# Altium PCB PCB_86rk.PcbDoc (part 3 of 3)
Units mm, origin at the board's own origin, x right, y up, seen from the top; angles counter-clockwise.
Board outline 185 x 150 mm, 2 copper layers (Top Layer, Bottom Layer); 95 components, 233 nets, 810 pads, 336 vias.
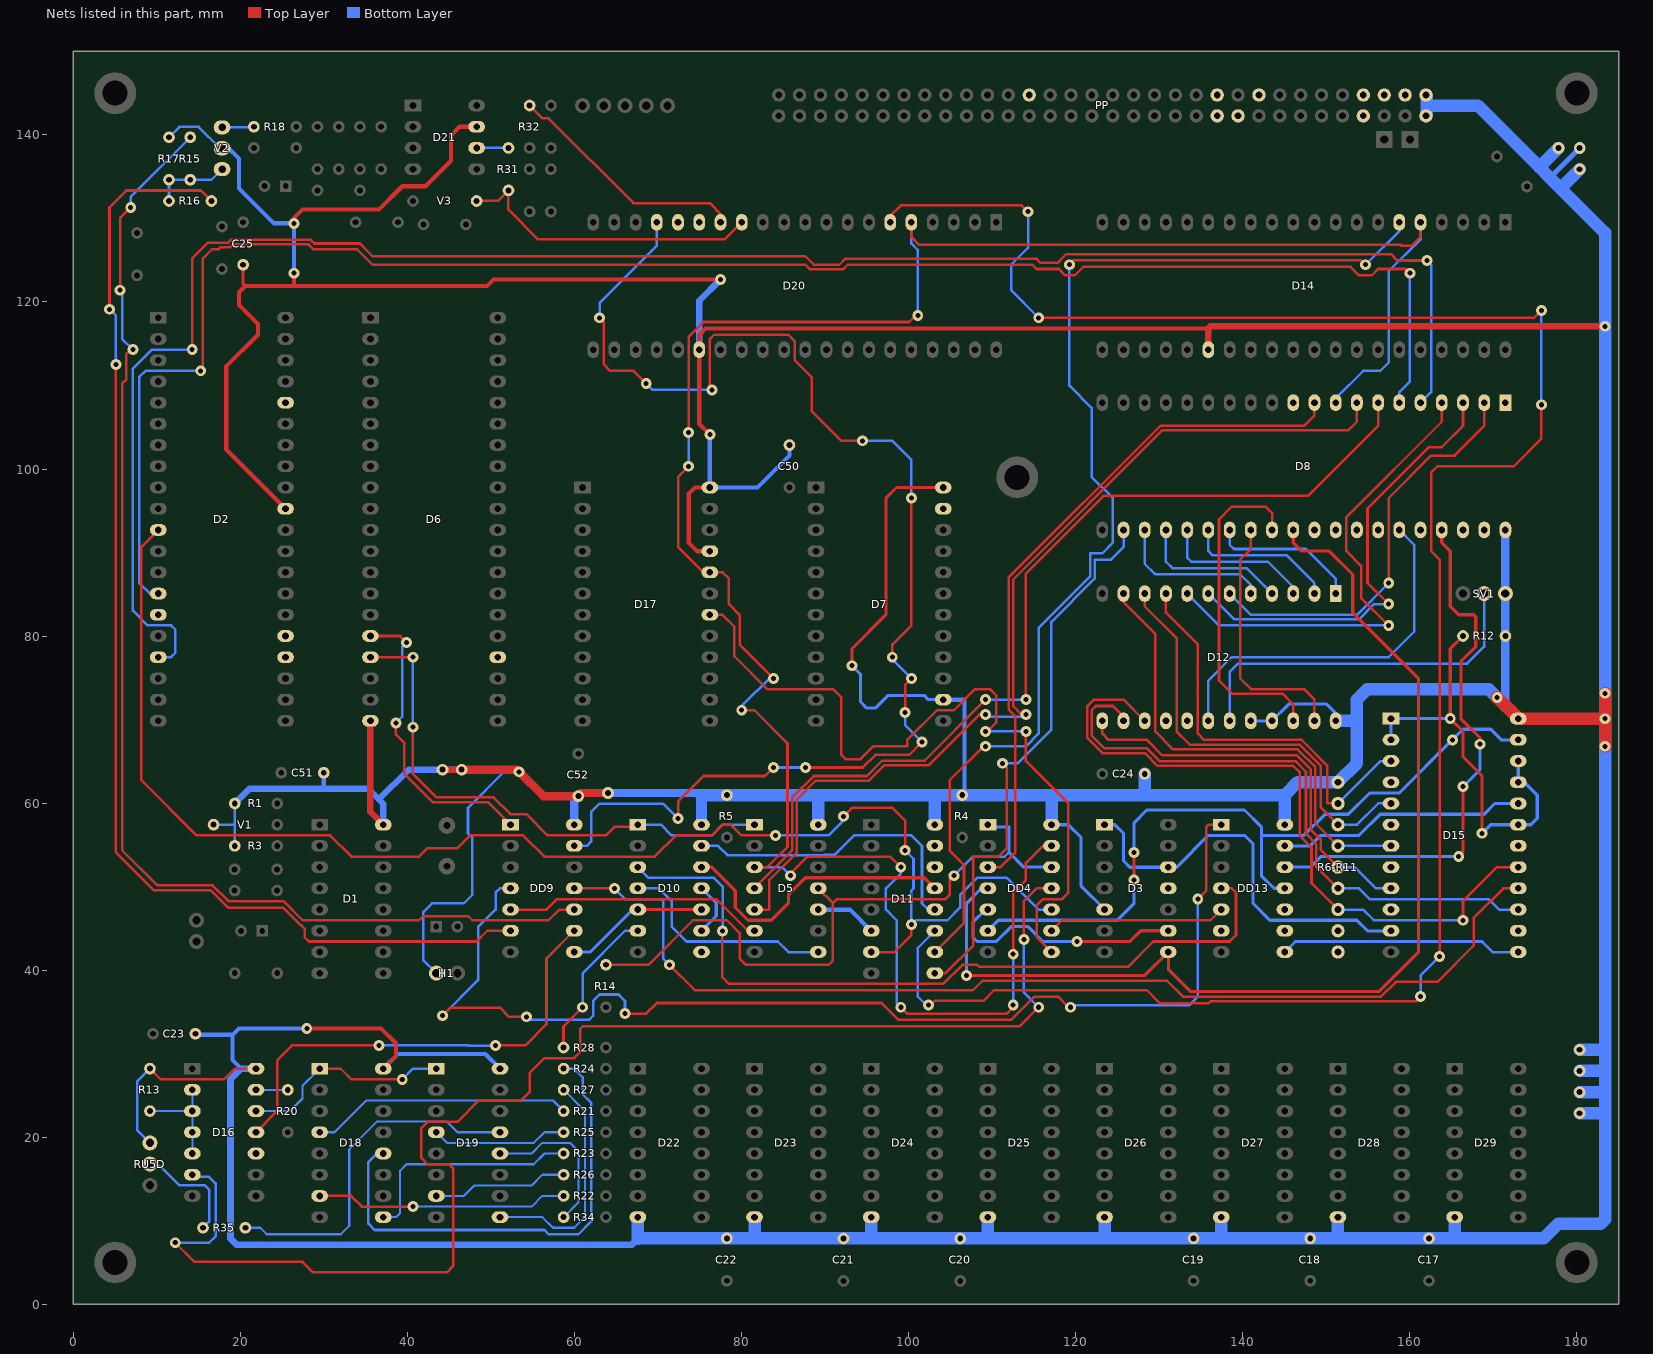
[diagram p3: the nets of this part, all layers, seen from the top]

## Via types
v1: diameter 1.3, hole 0.6, Top Layer to Bottom Layer, tented both sides, 301 vias
v2: diameter 1.4, hole 0.7, Top Layer to Bottom Layer, 27 vias
v3: diameter 1.4, hole 0.7, Top Layer to Bottom Layer, tented both sides, 4 vias
v4: diameter 3.2, hole 2.6, Top Layer to Bottom Layer, 2 vias
v5: diameter 1.6, hole 0.8, Top Layer to Bottom Layer, 1 vias
v6: diameter 1.6, hole 0.8, Top Layer to Bottom Layer, tented both sides, 1 vias

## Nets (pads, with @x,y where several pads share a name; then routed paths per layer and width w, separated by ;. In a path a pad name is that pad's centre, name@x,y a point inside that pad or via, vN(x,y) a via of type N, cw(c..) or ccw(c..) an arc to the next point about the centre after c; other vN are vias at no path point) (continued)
NetD2_11: D2.11 D11.7 DD4.10 | length 174
  Top Layer w0.305: D2.11@10.16,92.71 8.128,90.678 8.128,62.738 14.732,56.134 30.734,56.134 33.274,53.594 41.402,53.594 42.418,54.61 45.974,54.61 47.498,56.134 53.848,56.134 56.388,53.594 69.596,53.594 72.136,56.134 76.454,56.134 77.724,57.404 78.74,57.404 80.01,56.134 v1(84.074,56.134) ; v1(92.202,58.42) 93.218,59.436 98.044,59.436 99.568,57.912 v1(99.568,54.356) ; D11.7@95.52,42.18 95.536,42.164 98.298,42.164 100.33,44.196 v1(100.33,45.466)
  Bottom Layer w0.305: v1(84.074,56.134) 90.424,56.134 92.202,57.912 v1(92.202,58.42) ; v1(99.568,54.356) 100.584,53.34 100.584,49.784 100.33,49.53 v1(100.33,45.466) 100.838,45.974 104.648,45.974 106.172,47.498 106.172,49.022 108.204,51.054 111.76,51.054 115.554,47.26 DD4.10@117.11,47.26
NetD2_14: D2.14 D8.6 | length 213.3
  Top Layer w0.305: v1(15.24,111.76) 15.494,112.014 15.494,125.222 16.561,126.289 17.345,126.289 17.599,126.543 18.736,126.543 19.079,126.886 28.165,126.886 28.762,126.289 33.985,126.289 35.814,124.46 87.63,124.46 88.189,123.901 92.151,123.901 92.71,124.46 114.808,124.46 115.316,123.952 117.983,123.952 118.745,123.19 119.888,123.19 120.904,124.206 152.908,124.206 153.924,123.19 155.448,123.19 156.21,123.952 159.512,123.952 v1(160.02,123.444)
  Bottom Layer w0.305: D2.14@10.16,85.09 9.144,85.09 7.874,86.36 7.874,110.998 8.636,111.76 v1(15.24,111.76) ; D8.6@158.75,107.95 158.75,109.22 160.02,110.49 v1(160.02,123.444)
NetD2_15: D2.15
NetD2_17: D2.17 D8.5 | length 228
  Top Layer w0.305: v1(14.224,114.3) 14.224,125.222 16.104,127.102 18.505,127.102 18.848,127.444 28.396,127.444 28.841,127 34.29,127 35.814,125.476 87.63,125.476 88.646,124.46 91.694,124.46 92.405,125.171 115.316,125.171 115.814,124.674 117.816,124.674 118.872,125.73 157.734,125.73 158.496,124.968 v1(162.052,124.968)
  Bottom Layer w0.305: D2.17@10.16,77.47 11.684,77.47 12.192,77.978 12.192,80.772 11.684,81.28 8.89,81.28 7.112,83.058 7.112,112.014 9.398,114.3 v1(14.224,114.3) ; D8.5@161.29,107.95 162.56,109.22 162.56,124.46 v1(162.052,124.968)
NetD2_24: D2.24
NetD2_25: D2.25
NetD2_36: D2.36
NetD3_1: D3.1 D3.12 D15.11 | length 48.8
  Bottom Layer w0.381: D3.1@123.46,57.42 124.698,57.42 125.73,56.388 125.73,53.086 126.492,52.324 131.064,52.324 D3.12@131.08,52.34 132.096,52.34 135.89,56.134 140.208,56.134 141.224,55.118 141.224,48.006 143.256,45.974 153.67,45.974 154.94,44.704 157.734,44.704 D15.11@157.75,44.72
NetD3_8: D3.8 D8.30 DD4.4 | length 131
  Top Layer w0.381: v1(106.934,39.37) 128.27,39.37 D3.8@131.08,42.18 131.096,42.164 131.096,40.1 133.769,37.427 156.299,37.427 161.036,42.164 161.036,74.93 153.162,82.804 153.162,87.376 150.368,90.17 147.066,90.17 146.05,91.186 D8.30@146.05,92.71
  Bottom Layer w0.381: v1(106.934,39.37) 106.934,48.006 108.728,49.8 DD4.4@109.49,49.8
NetD3_9: D3.9 DD4.5 | length 29.8
  Top Layer w0.381: v1(120.142,43.434) 126.492,43.434 127.778,44.72 D3.9@131.08,44.72
  Bottom Layer w0.381: DD4.5@109.49,47.26 109.236,47.26 107.696,45.72 107.696,43.942 108.204,43.434 110.49,43.434 112.268,45.212 114.3,45.212 116.078,43.434 v1(120.142,43.434)
NetD3_11: D3.11
NetD5_1: D5.1 D6.17 D10.1 | length 64.6
  Top Layer w0.305: D6.17@35.56,77.47 v1(40.64,77.47) ; v1(40.64,69.088) 40.64,63.508 43.467,60.681 50.317,60.681 52.324,58.674 54.229,58.674 56.769,56.134 63.754,56.134 64.77,57.15 67.31,57.15 D10.1@67.58,57.42
  Bottom Layer w0.305: v1(40.64,69.088) v1(40.64,77.47) ; D10.1@67.58,57.42 70.342,57.42 71.628,56.134 76.454,56.134 77.74,57.42 D5.1@81.55,57.42
NetD5_3: D5.3 D8.9 D14.5 D17.20 D20.5 DD4.13 | length 284.2
  Top Layer w0.305: v1(73.66,100.33) 72.39,99.06 72.39,90.678 75.438,87.63 D17.20@76.2,87.63 77.724,87.63 78.486,86.868 78.486,83.82 79.756,82.55 79.756,78.994 v1(83.82,74.93) ; v1(73.66,104.394) 73.66,115.824 75.438,117.602 100.076,117.602 v1@101.092,118.618 ; v1(80.01,71.12) 81.534,71.12 85.496,67.158 85.496,54.762 83.074,52.34 D5.3@81.55,52.34 ; v1(85.852,51.308) 85.852,51.562 87.884,53.594 97.79,53.594 v1(99.06,52.324) ; v1(99.06,35.56) 99.862,34.758 111.72,34.758 v1@112.522,35.56 ; D20.5@100.33,129.54 100.33,127.762 101.244,126.848 158.902,126.848 159.004,126.746 160.274,126.746 161.29,127.762 D14.5@161.29,129.54 ; v1@113.03,41.91 112.522,42.418 112.522,49.276 114.046,50.8 114.046,52.832 116.094,54.88 DD4.13@117.11,54.88
  Bottom Layer w0.305: v1(73.66,100.33) v1(73.66,104.394) ; v1(80.01,71.12) 80.01,71.628 83.566,75.184 v1(83.82,74.93) ; D5.3@81.55,52.34 84.82,52.34 v1(85.852,51.308) ; v1(99.06,35.56) 98.552,36.068 98.552,45.974 97.282,47.244 97.282,49.784 99.06,51.562 v1(99.06,52.324) ; D20.5@100.33,129.54 100.33,127 101.092,126.238 v1(101.092,118.364) ; v1@112.522,35.56 v1(112.522,35.814) v1(112.522,41.91) ; D8.9@151.13,107.95 151.13,108.458 154.432,111.76 156.464,111.76 157.48,112.776 157.48,123.698 161.29,127.508 D14.5@161.29,129.54
NetD5_4: D5.4 D8.7 | length 112.9
  Top Layer w0.305: D5.4@81.55,49.8 81.55,49.828 86.055,54.333 86.055,60.655 88.646,63.246 94.996,63.246 96.825,65.075 101.905,65.075 v1(109.22,72.39) ; v1(114.046,72.39) 114.046,87.489 123.331,96.774 147.828,96.774 156.21,105.156 D8.7@156.21,107.95
  Bottom Layer w0.305: v1(109.22,72.39) v1(114.046,72.39)
NetD5_5: D5.5 D8.8 | length 116.3
  Top Layer w0.305: D5.5@81.55,47.26 83.328,47.26 83.312,47.276 83.312,50.8 86.614,54.102 86.614,60.424 88.877,62.687 95.227,62.687 97.056,64.516 102.362,64.516 108.458,70.612 v1(109.22,70.612) ; v1(114.046,70.612) 113.538,70.612 112.522,71.628 112.522,86.755 130.415,104.648 152.654,104.648 153.67,105.664 D8.8@153.67,107.95
  Bottom Layer w0.305: v1@109.22,70.358 v1@114.046,70.358
NetD5_6: D5.6 DD9.5 | length 31.3
  Top Layer w0.305: DD9.5@52.34,47.26 56.658,47.26 57.912,48.514 76.962,48.514 80.756,44.72 D5.6@81.55,44.72
NetD5_8: D5.8 D10.4 | length 26.5
  Bottom Layer w0.305: D10.4@67.58,49.8 70.088,49.8 71.628,48.26 71.628,45.212 73.406,43.434 84.328,43.434 85.598,42.164 89.154,42.164 D5.8@89.17,42.18
NetD5_10: D5.10 D11.6 | length 7.7
  Bottom Layer w0.381: D5.10@88.916,47.26 D5.10@89.17,47.26
  Bottom Layer w0.508: D5.10@89.17,47.26 89.186,47.244 92.964,47.244 95.488,44.72 D11.6@95.52,44.72
NetD5_11: D5.11 DD4.1 DD4.12 R14.2 | length 79.1
  Top Layer w0.305: R14.2@63.754,40.64 68.834,40.64 74.168,45.974 78.232,45.974 79.756,44.45 79.756,41.402 80.518,40.64 90.424,40.64 90.932,41.148 90.932,48.038 ; D5.11@89.17,49.8 90.932,48.038 ; v1(105.41,51.308) 104.902,50.8 104.902,49.022 104.394,48.514 91.408,48.514 90.932,48.038
  Bottom Layer w0.305: v1(105.41,51.308) 107.696,53.594 111.506,53.594 112.014,54.102 112.014,57.15
  Bottom Layer w0.381: DD4.1@109.49,57.42 109.76,57.15 112.014,57.15 ; 112.014,54.102 113.776,52.34 DD4.12@117.11,52.34
NetD6_16: D6.16 DD9.1 | length 36.7
  Top Layer w0.305: D6.16@35.56,80.01 39.116,80.01 v1@40.005,79.121 ; v1(38.608,69.596) 38.608,68.199 39.624,67.183 39.624,63.5 43.002,60.122 49.638,60.122 DD9.1@52.34,57.42
  Bottom Layer w0.305: v1(38.608,69.596) 39.37,70.358 39.37,78.74 v1(39.878,79.248)
NetD6_24: D6.24
NetD7_23: D7.23
NetD8_1: D8.1
NetD8_2: D8.2 D12.6 | length 49.6
  Top Layer w0.305: v1(157.48,86.36) 157.48,96.52 162.56,101.6 165.354,101.6 168.91,105.156 D8.2@168.91,107.95
  Bottom Layer w0.305: D12.6@138.43,85.09 140.97,82.55 153.67,82.55 v1(157.48,86.36)
NetD8_3: D8.3 D12.7 | length 54.4
  Top Layer w0.305: v1(157.48,83.82) 154.94,86.36 154.94,95.25 162.306,102.616 163.83,102.616 166.37,105.156 D8.3@166.37,107.95
  Bottom Layer w0.305: D12.7@135.89,85.09 138.989,81.991 153.901,81.991 155.73,83.82 v1(157.48,83.82)
NetD8_4: D8.4 D12.8 | length 59.2
  Top Layer w0.305: v1(157.48,81.28) 154.178,84.582 154.178,88.392 152.4,90.17 152.4,94.234 163.83,105.664 D8.4@163.83,107.95
  Bottom Layer w0.305: D12.8@133.35,85.09 137.16,81.28 v1(157.48,81.28)
NetD8_10: D8.10 DD4.3 | length 83.4
  Top Layer w0.305: DD4.3@109.49,52.34 111.014,52.34 112.776,54.102 112.776,70.388 111.963,71.201 111.963,86.986 130.184,105.207 147.371,105.207 148.59,106.426 D8.10@148.59,107.95
NetD8_11: D8.11
NetD8_22: D8.22 D11.9 | length 67.5
  Top Layer w0.305: D11.9@103.14,39.64 104.41,39.64 107.747,42.977 107.747,53.594 110.744,53.594 111.76,54.61 111.76,64.262 v1(111.252,64.77)
  Bottom Layer w0.305: v1(111.252,64.77) 113.03,64.77 117.094,68.834 117.094,81.703 122.276,86.885 122.276,89.154 124.206,89.154 125.73,90.678 D8.22@125.73,92.71
NetD8_23: D8.23 D12.5 | length 18.8
  Bottom Layer w0.305: D8.23@128.27,92.71 128.27,88.646 129.54,87.376 139.7,87.376 140.97,86.106 D12.5@140.97,85.09
NetD8_24: D8.24 D12.4 | length 18.1
  Bottom Layer w0.305: D8.24@130.81,92.71 130.81,88.9 131.572,88.138 140.462,88.138 D12.4@143.51,85.09
NetD8_25: D8.25 D12.3 | length 18.2
  Bottom Layer w0.305: D8.25@133.35,92.71 133.35,89.408 133.858,88.9 143.002,88.9 146.05,85.852 D12.3@146.05,85.09
NetD8_26: D8.26 D12.2 | length 18.1
  Bottom Layer w0.305: D8.26@135.89,92.71 135.89,90.17 136.398,89.662 145.288,89.662 148.59,86.36 D12.2@148.59,85.09
NetD8_27: D8.27 D12.1 | length 17.9
  Bottom Layer w0.305: D8.27@138.43,92.71 138.43,90.932 138.938,90.424 147.574,90.424 151.13,86.868 D12.1@151.13,85.09
NetD8_28: D8.28 D12.23 | length 30.8
  Top Layer w0.305: D8.28@140.97,92.71 140.97,90.424 139.7,89.154 139.7,74.93 140.97,73.66 147.32,73.66 148.59,72.39 D12.23@148.59,69.85
NetD8_29: D8.29 D12.22 | length 40.7
  Top Layer w0.305: D8.29@143.51,92.71 143.51,94.742 142.748,95.504 138.684,95.504 137.16,93.98 137.16,74.676 138.735,73.101 144.78,73.101 146.05,71.831 D12.22@146.05,69.85
NetD8_31: D8.31
NetD8_32: D8.32
NetD8_33: D8.33
NetD8_34: D8.34
NetD8_35: D8.35 D12.18 | length 44.8
  Bottom Layer w0.305: D12.18@135.89,69.85 135.89,74.676 138.684,77.47 157.48,77.47 160.528,80.518 160.528,90.932 D8.35@158.75,92.71
NetD8_36: D8.36
NetD8_37: D8.37 DD13.12 | length 65.9
  Top Layer w0.381: D8.37@163.83,92.71 163.83,91.186 164.846,90.17 164.846,83.566 165.862,82.55 167.64,82.55 167.894,82.296 167.894,78.74 166.116,76.962 166.116,70.104 168.402,67.818 v1(168.402,67.056) ; v1(165.862,53.594) 166.37,54.102 v1(166.37,61.976)
  Bottom Layer w0.381: DD13.12@145.05,52.34 148.098,52.34 149.352,53.594 v1(165.862,53.594) ; v1(166.37,61.976) 168.402,64.008 v1(168.402,67.056)
NetD8_38: D8.38
NetD8_39: D8.39
NetD10_3: D10.3 DD13.4 | length 93.5
  Top Layer w0.305: v1(77.724,44.704) 77.684,44.664 77.684,39.156 78.486,38.354 104.14,38.354 106.426,40.64 108.204,40.64 108.458,40.386 126.238,40.386 129.286,43.434 138.43,43.434 139.192,44.196 139.192,49.276 138.684,49.784 137.446,49.784 DD13.4@137.43,49.8
  Bottom Layer w0.305: D10.3@67.58,52.34 68.866,51.054 76.708,51.054 77.724,50.038 v1(77.724,44.704)
NetD10_5: D10.5 D10.10 DD9.8 | length 17.3
  Top Layer w0.381: D10.5@67.58,47.26 D10.10@75.2,47.26
  Bottom Layer w0.381: DD9.8@59.96,42.18 61.865,42.18 66.945,47.26 D10.5@67.58,47.26
NetD10_6: D10.6 R28.2 | length 18.6
  Top Layer w0.305: R28.2@58.674,30.734 58.674,33.274 v1(60.96,35.56)
  Bottom Layer w0.305: v1(60.96,35.56) 60.96,39.624 66.056,44.72 D10.6@67.58,44.72
NetD10_8: D10.8
NetD10_9: D10.9 D10.11 | length 6.5
  Bottom Layer w0.381: D10.9@75.2,44.72 76.962,46.482 76.962,48.038 D10.11@75.2,49.8
NetD10_12: D10.12 D11.13 | length 35
  Top Layer w0.381: D10.12@75.2,52.34 76.438,52.34 79.248,49.53 79.248,47.498 80.772,45.974 83.566,45.974 85.598,48.006 85.598,49.022 87.63,51.054 101.886,51.054 D11.13@103.14,49.8
NetD10_13: D10.13 D11.12 | length 37.1
  Bottom Layer w0.305: D10.13@75.2,54.88 77.2,54.88 78.306,53.774 89.928,53.774 89.959,53.805 91.143,53.805 93.472,56.134 100.33,56.134 101.6,54.864 101.6,48.006 102.346,47.26 D11.12@103.14,47.26
NetD11_10: D11.10 D14.6 | length 141.2
  Top Layer w0.305: D11.10@103.14,42.18 106.629,45.669 106.629,52.578 104.902,54.305 104.902,62.738 108.966,66.802 v1(109.22,66.802) ; v1(119.253,124.46) 119.812,125.019 154.127,125.019 v1(154.686,124.46)
  Bottom Layer w0.305: v1(109.22,66.802) 114.046,66.802 115.57,68.326 115.57,80.969 121.717,87.116 121.717,89.916 123.19,89.916 124.46,91.186 124.46,96.52 121.92,99.06 121.92,107.315 119.253,109.982 v1(119.253,124.46) ; v1(154.686,124.46) 158.75,128.524 D14.6@158.75,129.54
NetD11_11: D11.11 D20.6 | length 259.3
  Top Layer w0.305: D20.6@97.79,129.54 97.79,130.302 99.06,131.572 113.538,131.572 v1(114.3,130.81) ; v1@102.362,35.56 103.124,36.322 108.966,36.322 110.236,37.592 128.524,37.592 130.088,36.028 135.923,36.028 136.167,36.271 160.731,36.271 v1(161.29,36.83) ; v1(115.57,118.11) 174.879,118.11 175.387,118.618 v1@175.768,118.618 ; v1(163.576,41.656) 163.576,89.154 162.56,90.17 162.56,99.568 163.322,100.33 172.466,100.33 175.768,103.632 v1(175.768,107.696)
  Bottom Layer w0.305: v1@102.362,35.56 101.092,36.83 101.092,42.672 D11.11@103.14,44.72 ; v1(114.3,130.81) 114.3,126.492 112.268,124.46 112.268,121.412 v1(115.57,118.11) ; v1(161.29,36.83) 161.29,39.37 v1(163.576,41.656) ; v1@175.768,107.442 v1(175.768,107.696) v1(175.768,118.999)
  other v1: 102.362,35.814
NetD11_14: D11.14
NetD11_15: D11.15
NetD12_9: D12.9 D15.3 R6-R11.2 | length 49.7
  Top Layer w0.305: D12.9@130.81,85.09 130.81,82.804 134.62,78.994 134.62,68.326 135.382,67.564 147.066,67.564 150.114,64.516 150.114,59.976 150.098,59.96 R6-R11.2@151.4,59.96
  Bottom Layer w0.305: R6-R11.2@151.4,59.96 156.48,65.04 D15.3@157.75,65.04
NetD12_10: D12.10 D15.5 R6-R11.3 | length 52.4
  Top Layer w0.305: D12.10@128.27,85.09 128.27,83.566 132.08,79.756 132.08,68.58 133.655,67.005 146.812,67.005 149.352,64.465 149.352,59.468 R6-R11.3@151.4,57.42
  Bottom Layer w0.305: R6-R11.3@151.4,57.42 153.686,57.42 156.226,59.96 D15.5@157.75,59.96
NetD12_11: D12.11 D15.7 R6-R11.4 | length 55.9
  Top Layer w0.305: D12.11@125.73,85.09 125.73,84.074 129.54,80.264 129.54,68.58 131.674,66.446 146.558,66.446 148.692,64.313 148.692,57.588 R6-R11.4@151.4,54.88
  Bottom Layer w0.305: R6-R11.4@151.4,54.88 D15.7@157.75,54.88
NetD12_13: D12.13 D15.9 R6-R11.5 | length 48.7
  Top Layer w0.305: D12.13@123.19,69.85 123.19,68.326 123.952,67.564 128.524,67.564 130.367,65.721 146.493,65.721 148.133,64.081 148.133,56.845 149.352,55.626 149.352,54.388 R6-R11.5@151.4,52.34
  Bottom Layer w0.305: R6-R11.5@151.4,52.34 153.4,52.34 155.956,49.784 157.734,49.784 D15.9@157.75,49.8
NetD12_14: D12.14 D15.15 R6-R11.6 | length 73.7
  Top Layer w0.305: D12.14@125.73,69.85 125.73,70.358 124.46,71.628 122.428,71.628 121.92,71.12 121.92,68.072 123.444,66.548 128.524,66.548 130.048,65.024 146.304,65.024 147.574,63.754 147.574,56.337 148.793,55.118 148.793,52.407 R6-R11.6@151.4,49.8
  Bottom Layer w0.305: R6-R11.6@151.4,49.8 153.908,49.8 155.194,48.514 169.418,48.514 170.688,47.244 172.974,47.244 D15.15@172.99,47.26
NetD12_15: D12.15 D15.17 R6-R11.7 | length 83.6
  Top Layer w0.305: D12.15@128.27,69.85 125.73,72.39 122.174,72.39 121.361,71.577 121.361,67.841 123.213,65.989 128.293,65.989 129.817,64.465 146.05,64.465 146.812,63.703 146.812,56.134 148.234,54.712 148.234,50.426 R6-R11.7@151.4,47.26 ; v1(166.37,45.974) 166.37,48.26 170.45,52.34 D15.17@172.99,52.34
  Bottom Layer w0.305: R6-R11.7@151.4,47.26 154.416,47.26 155.702,45.974 v1(166.37,45.974)
NetD12_16: D12.16
NetD12_17: D12.17
NetD12_19: D12.19 SV1.2 | length 43.9
  Bottom Layer w0.305: D12.19@138.43,69.85 138.43,75.692 139.446,76.708 166.878,76.708 168.91,78.74 SV1.2@168.91,85.09
NetD15_1: D15.1 D15.2 D15.19 D15.21 D15.22 R12.2 | length 52.2
  Top Layer w0.381: R12.2@166.37,80.01 164.846,78.486 v1(164.846,70.12) 166.37,68.596 166.37,65.532 168.656,63.246 v1(168.656,56.388)
  Bottom Layer w0.381: D15.2@157.75,67.58 D15.1@157.75,70.12 ; D15.1@158.274,69.596 D15.1@157.75,70.12 ; v1(164.846,70.12) D15.1@157.75,70.12 ; v1(168.656,56.388) 169.688,57.42 D15.19@172.99,57.42 173.006,57.404 174.498,57.404 175.26,58.166 175.26,60.96 173.72,62.5 D15.21@172.99,62.5 ; D15.22@172.752,65.278 D15.22@172.99,65.04 D15.21@172.99,62.5 ; D15.21@173.006,62.484 D15.21@172.99,62.5
NetD15_4: D15.4
NetD15_6: D15.6
NetD15_8: D15.8
NetD15_10: D15.10
NetD15_13: D15.13 DD13.8 | length 29
  Bottom Layer w0.305: DD13.8@145.05,42.18 146.304,43.434 168.656,43.434 169.926,42.164 172.974,42.164 D15.13@172.99,42.18
NetD15_14: D15.14
NetD15_16: D15.16 DD9.11 | length 130.7
  Top Layer w0.305: DD9.11@59.96,49.8 59.976,49.784 v1(64.77,49.784) ; v1(71.374,40.64) 74.422,37.592 107.696,37.592 108.814,38.71 130.962,38.71 132.842,36.83 156.546,36.83 158.324,38.608 163.322,38.608 167.64,42.926 167.64,46.228 171.212,49.8 D15.16@172.99,49.8
  Bottom Layer w0.305: v1(64.77,49.784) 66.04,48.514 70.358,48.514 70.612,48.26 70.612,41.402 v1(71.374,40.64)
NetD15_18: D15.18
NetD15_20: D15.20 DD13.13 | length 30
  Bottom Layer w0.381: DD13.13@145.05,54.88 148.098,54.88 149.352,56.134 153.924,56.134 156.464,58.674 168.91,58.674 170.196,59.96 D15.20@172.99,59.96
NetD15_23: D15.23 DD4.6 DD13.11 | length 91.1
  Top Layer w0.381: v1(127,50.8) v1(127,54.102)
  Bottom Layer w0.381: DD4.6@109.49,44.72 110.744,45.974 124.968,45.974 127,48.006 v1(127,50.8) ; v1(127,54.102) 127,57.658 128.524,59.182 140.208,59.182 142.24,57.15 142.24,56.134 ; DD13.11@145.05,49.8 143.748,49.8 142.24,51.308 142.24,56.134 ; D15.23@172.99,67.58 172.974,67.564 170.942,67.564 169.672,68.834 166.37,68.834 v1(165.1,67.564) 158.75,61.214 155.194,61.214 152.654,58.674 149.86,58.674 147.32,56.134 142.24,56.134
NetD16_2: D16.2 D16.3 D16.4 D16.5 R13.1 | length 12.7
  Bottom Layer w0.254: R13.1@9.16,23.13 D16.3@14.24,23.13 ; D16.5@14.24,18.05 D16.4@14.24,20.59 D16.3@14.24,23.13 ; D16.2@14.24,25.67 D16.3@14.24,23.13
NetD16_6: D16.6 DD4.11 | length 169.1
  Top Layer w0.305: v1(12.192,7.366) 14.478,5.08 27.432,5.08 28.702,3.81 44.704,3.81 45.466,4.572 45.466,16.256 44.958,16.764 42.418,16.764 41.656,17.526 41.656,21.082 42.418,21.844 45.974,21.844 48.514,24.384 53.594,24.384 54.61,25.4 54.61,27.686 56.388,29.464 59.944,29.464 60.681,30.201 60.681,32.972 60.983,33.274 113.284,33.274 v1(115.57,35.56) ; v1(113.792,43.688) 113.792,48.26 115.332,49.8 DD4.11@117.11,49.8
  Bottom Layer w0.305: v1@12.7,7.366 16.256,7.366 17.018,8.128 17.018,14.478 16.256,15.24 14.51,15.24 D16.6@14.24,15.51 ; v1(113.792,43.688) 113.792,37.338 v1(115.57,35.56)
NetD16_10: D16.10
NetD16_11: D16.11 DD9.9 | length 56.3
  Top Layer w0.305: D16.11@21.86,20.59 24.384,23.114 24.384,29.21 26.162,30.988 v1(36.576,30.988) ; v1(50.546,30.988) 54.102,30.988 56.642,33.528 56.642,41.402 DD9.9@59.96,44.72
  Bottom Layer w0.305: v1(36.576,30.988) 47.274,30.988 47.314,30.948 50.506,30.948 v1(50.546,30.988)
NetD16_12: D16.12 D18.1 D19.1 | length 25.7
  Top Layer w0.305: D18.1@29.48,28.21 29.496,28.194 32.004,28.194 33.274,26.924 v1(39.37,26.924)
  Bottom Layer w0.254: D16.12@21.86,23.13 25.924,23.13 27.432,24.638 27.432,26.162 D18.1@29.48,28.21
  Bottom Layer w0.305: v1(39.37,26.924) 40.656,28.21 D19.1@43.45,28.21
NetD16_13: D16.13 R20.2 | length 3.8
  Bottom Layer w0.254: D16.13@21.86,25.67 R20.2@25.67,25.67
NetD17_18: D17.18 DD4.8 | length 93.7
  Top Layer w0.305: D17.18@76.2,82.55 77.724,82.55 79.121,81.153 79.121,77.597 83.058,73.66 90.932,73.66 91.948,72.644 91.948,65.786 92.456,65.278 94.234,65.278 95.758,66.802 99.822,66.802 99.822,67.564 103.378,71.12 105.41,71.12 107.95,73.66 109.728,73.66 110.49,72.898 110.49,69.647 109.423,68.58 v1(109.22,68.58) ; v1(114.046,68.58) 114.046,65.024 119.126,59.944 119.126,49.276 118.364,48.514 116.078,48.514 115.316,47.752 115.316,43.974 DD4.8@117.11,42.18
  Bottom Layer w0.305: v1(109.22,68.58) v1(114.046,68.58)
NetD18_4: D18.4 R21.2 | length 31.3
  Bottom Layer w0.254: D18.4@29.48,20.59 31.258,20.59 35.068,24.4 57.42,24.4 R21.2@58.69,23.13
NetD18_7: D18.7 R22.2 | length 30.3
  Top Layer w0.305: D18.7@29.48,12.97 33.258,12.97 34.544,11.684 v1(40.64,11.684)
  Bottom Layer w0.254: v1(40.64,11.684) 54.864,11.684 56.15,12.97 R22.2@58.69,12.97
NetD18_9: D18.9 R23.2 | length 27.7
  Bottom Layer w0.254: D18.9@37.116,10.414 D18.9@37.1,10.43 38.624,10.43 39.116,10.922 39.116,16.002 39.878,16.764 55.118,16.764 56.404,18.05 R23.2@58.69,18.05
NetD18_12: D18.12 R24.2 | length 57.8
  Bottom Layer w0.305: D18.12@37.1,18.05 36.338,18.05 35.306,17.018 35.306,9.652 36.068,8.89 56.388,8.89 56.896,8.382 60.452,8.382 61.976,9.906 61.976,24.13 60.96,25.146 60.96,27.178 59.944,28.194 58.706,28.194 R24.2@58.69,28.21
NetD19_4: D19.4 R25.2 | length 16.3
  Bottom Layer w0.254: D19.4@43.45,20.59 44.72,19.32 55.134,19.32 56.404,20.59 R25.2@58.69,20.59
NetD19_7: D19.7 R26.2 | length 16.3
  Bottom Layer w0.254: D19.7@43.45,12.97 43.466,12.954 46.736,12.954 48.006,14.224 54.864,14.224 56.15,15.51 R26.2@58.69,15.51
NetD19_9: D19.9 R27.2 | length 27.5
  Bottom Layer w0.254: D19.9@51.07,10.43 56.15,10.43 57.42,9.16 59.96,9.16 61.23,10.43 61.23,23.13 R27.2@58.69,25.67
NetD19_12: D19.12 R34.2 | length 19
  Bottom Layer w0.254: D19.12@51.07,18.05 54.88,18.05 56.15,19.32 59.452,19.32 60.468,18.304 60.468,12.208 R34.2@58.69,10.43
NetD19_13: D19.13 R35.1 | length 42.3
  Bottom Layer w0.254: R35.1@20.59,9.16 22.368,9.16 23.146,8.382 32.004,8.382 33.02,9.398 33.02,18.542 36.338,21.86 44.72,21.86 45.99,20.59 D19.13@51.07,20.59
NetD20_13: D20.13 R31.1 V3.K | length 36.9
  Top Layer w0.305: V3.K@48.276,132.096 50.816,132.096 R31.1@52.086,133.366 52.086,131.048 55.626,127.508 77.978,127.508 D20.13@80.01,129.54
NetD20_14: D20.14 R32.2 | length 29.2
  Top Layer w0.305: R32.2@54.626,143.526 56.166,141.986 56.896,141.986 67.056,131.826 76.2,131.826 77.47,130.556 D20.14@77.47,129.54
NetD20_15: D20.15
NetD20_16: D20.16
NetD20_17: D20.17 DD9.13 | length 163.1
  Top Layer w0.305: v1(62.992,118.11) 63.5,117.602 63.5,112.522 64.262,111.76 67.056,111.76 v1(68.58,110.236) ; v1(72.39,58.166) 72.39,60.198 75.438,63.246 82.804,63.246 v1(83.82,64.262) ; v1(76.454,109.474) 76.2,109.728 76.2,115.57 76.708,116.078 85.598,116.078 86.36,115.316 86.36,113.03 88.392,110.998 88.392,106.934 91.948,103.378 v1(94.488,103.378) ; v1(87.63,64.262) 94.488,64.262 96.012,65.786 100.076,65.786 v1(101.6,67.31) ; v1(98.044,77.47) 98.044,78.994 100.33,81.28 v1(100.33,96.52) ; v1(99.568,70.866) 99.568,74.168 v1(100.33,74.93)
  Bottom Layer w0.305: DD9.13@59.96,54.88 61.484,54.88 61.984,55.38 61.984,58.936 62.992,59.944 70.612,59.944 v1(72.39,58.166) ; v1(62.992,118.11) 62.992,119.888 69.85,126.746 D20.17@69.85,129.54 ; v1(68.58,110.236) 69.342,109.474 v1(76.454,109.474) ; v1(83.82,64.262) v1(87.63,64.262) ; v1(94.488,103.378) 98.044,103.378 100.33,101.092 v1(100.33,96.52) ; v1(98.044,77.47) 98.044,77.216 v1(100.33,74.93) ; v1(99.568,70.866) 99.568,69.342 v1(101.6,67.31)
NetD21_6: D21.6 R31.2 | length 3.8
  Bottom Layer w0.305: D21.6@48.276,138.446 R31.2@52.086,138.446
NetDD4_9: DD4.9 DD13.5 | length 21.4
  Top Layer w0.305: DD4.9@117.11,44.72 118.364,45.974 136.144,45.974 DD13.5@137.43,47.26
NetDD9_4: DD9.4 DD13.1 | length 141.2
  Top Layer w0.305: v1(44.196,34.544) 45.161,35.509 51.054,35.509 52.146,34.417 v1(54.229,34.417) ; v1(66.04,34.798) 68.58,34.798 69.85,36.068 96.774,36.068 98.806,34.036 112.268,34.036 115.062,36.83 117.856,36.83 119.126,35.56 v1(119.38,35.56) ; v1(134.62,48.514) 135.636,49.53 135.636,57.15 135.906,57.42 DD13.1@137.43,57.42
  Bottom Layer w0.305: v1(44.196,34.544) 48.463,38.811 48.463,45.161 50.546,47.244 50.546,49.276 51.054,49.784 52.324,49.784 DD9.4@52.34,49.8 ; v1(54.229,34.417) 54.61,34.036 61.722,34.036 62.23,34.544 62.23,36.322 62.992,37.084 65.278,37.084 66.04,36.322 v1(66.04,34.798) ; v1(119.38,35.56) 119.634,35.814 133.604,35.814 134.62,36.83 v1(134.62,48.514)
NetDD9_6: DD9.6 R16.1 | length 143.9
  Top Layer w0.305: v1(4.318,119.126) 4.318,131.318 6.35,133.35 15.272,133.35 R16.1@16.526,132.096 ; v1(5.08,112.522) 5.08,54.102 9.601,49.581 16.431,49.581 18.514,47.498 25.118,47.498 27.201,45.415 27.229,45.415 27.686,44.958 27.686,43.942 28.194,43.434 48.26,43.434 49.546,44.72 DD9.6@52.34,44.72
  Bottom Layer w0.305: v1(4.318,119.126) 5.08,118.364 v1(5.08,112.522)
NetDD9_10: DD9.10 R15.2 | length 148.8
  Top Layer w0.305: v1(5.588,121.412) 5.588,130.048 v1(6.858,131.318) ; v1@7.112,114.554 6.35,113.792 6.35,110.744 5.842,110.236 5.842,54.356 10.058,50.14 16.662,50.14 18.542,48.26 25.146,48.26 27.432,45.974 41.402,45.974 41.91,46.482 47.244,46.482 47.752,45.974 56.896,45.974 58.182,47.26 DD9.10@59.96,47.26
  Bottom Layer w0.305: v1(5.588,121.412) 5.842,121.158 5.842,115.57 v1(7.112,114.3) ; v1(6.858,131.318) 6.858,132.588 R15.2@13.986,139.716
NetDD13_6: DD13.6
NetDD13_9: DD13.9
NetDD13_10: DD13.10
NetPP_А13: PP.А13
NetPP_А22: PP.А22
NetPP_А24: PP.А24
NetPP_А29: PP.А29
NetPP_А30: PP.А30
NetPP_А31: PP.А31
NetPP_Б22: PP.Б22
NetPP_Б23: PP.Б23
NetPP_Б29: PP.Б29
NetR6-R11_8: R6-R11.8
NetR6-R11_9: R6-R11.9
NetR15_1: R15.1 R16.2 R17.1 V2.B | length 9.4
  Bottom Layer w0.305: R16.2@11.446,132.096 R17.1@11.446,134.636 R15.1@13.986,134.636 16.526,134.636 V2.B@17.796,135.906
NetR18_2: R18.2 V2.E | length 3.8
  Bottom Layer w0.305: V2.E@17.796,140.906 21.526,140.906 R18.2@21.606,140.986
NetR35_2: R35.2 RU5D.2 | length 13.2
  Bottom Layer w0.305: RU5D.2@9.16,16.78 9.43,16.51 10.414,16.51 12.7,14.224 15.748,14.224 16.256,13.716 16.256,9.906 R35.2@15.51,9.16
VCC: C17.1 C18.1 C19.1 C20.1 C21.1 C22.1 C23.1 C24.1 C25.1 C50.1 C51.1 C52.2 D1.16 D2.31 D3.5 D5.14 D6.20 D7.14 D7.24 D8.40 D10.14 D11.16 D12.20 D12.21 D12.24 D14.26 D15.24 D16.14 D17.21 D17.24 D18.16 D19.16 D20.26 D21.7 D22.8 D23.8 D24.8 D25.8 D26.8 D27.8 D28.8 D29.8 DD4.14 DD9.14 DD13.14 H1.2 PP.А32 PP.Б32 R1.2 R3.1 R4.2 R5.1 R6-R11.1 R12.1 R13.2 R17.2 RU5D.1 SV1.3 V1.K V2.C | length 1155.8
  Top Layer w0.305: R13.2@9.16,28.21 10.43,26.94 18.05,26.94 19.32,28.21 D16.14@21.86,28.21
  Top Layer w0.381: C25.1@20.32,124.46 20.32,122.174 20.574,121.92 ; v1(93.218,76.454) 93.218,78.486 97.282,82.55 97.282,96.52 98.552,97.79 D7.24@104.14,97.79
  Top Layer w0.508: D2.31@25.4,95.25 18.288,102.362 18.288,112.268 22.098,116.078 22.098,117.348 19.812,119.634 19.812,121.158 20.574,121.92 26.416,121.92 ; v1(26.416,123.444) 26.416,121.92 ; v1(26.416,129.413) 26.416,130.048 27.432,131.064 36.576,131.064 39.37,133.858 42.164,133.858 45.212,136.906 45.212,139.954 46.244,140.986 D21.7@48.276,140.986 ; v1(27.94,33.02) 36.83,33.02 38.608,31.242 38.608,29.718 D18.16@37.1,28.21 ; D17.21@76.2,90.17 74.676,90.17 73.66,91.186 73.66,97.028 74.422,97.79 D17.24@76.2,97.79 ; v1(76.2,104.14) 74.93,105.41 D20.26@74.93,114.3 74.93,116.078 75.692,116.84 135.89,116.84 ; v1(77.47,122.682) 50.292,122.682 49.53,121.92 26.416,121.92
  Top Layer w0.762: D6.20@35.56,69.85 35.56,58.96 D1.16@37.1,57.42 ; v3(44.196,64.008) v2(46.482,64.008)
  Top Layer w0.8: D14.26@135.89,114.3 135.89,116.84 136.144,117.094 v1(183.388,117.094)
  Top Layer w1: v2(46.482,64.008) 53.086,64.008 v1(53.34,63.754) 56.261,60.833 C52.2@60.452,60.833 60.833,61.214 61.214,61.214 v2(64.008,61.214)
  Top Layer w1.5: v1@170.434,72.644 v1(170.466,72.644) D15.24@172.99,70.12 183.372,70.12 v1(183.388,70.104) ; v1(183.388,66.802) v1(183.388,70.104) ; v1(183.388,73.152) v1(183.388,70.104)
  Bottom Layer w0.305: RU5D.1@9.16,19.32 7.636,20.844 7.636,26.686 R13.2@9.16,28.21 ; R17.2@11.446,139.716 12.7,140.97 14.986,140.97 17.55,138.406 V2.C@17.796,138.406 ; V1.K@16.78,57.42 19.32,57.42 ; R3.1@19.32,54.88 19.32,57.42 ; R1.2@19.32,59.96 19.32,57.42 ; H1.2@43.45,39.64 41.91,41.18 41.91,46.99 42.926,48.006 46.736,48.006 47.752,49.022 47.752,55.88 47.244,56.388 47.244,59.436 51.562,63.754 v1(53.34,63.754)
  Bottom Layer w0.381: v1(93.218,76.454) 94.234,75.438 94.234,72.136 94.996,71.374 96.012,71.374 97.536,72.898 101.854,72.898 102.362,72.39 D7.14@104.14,72.39 ; DD4.14@117.11,57.42 119.11,57.42 120.65,55.88 120.65,50.07 D3.5@123.46,47.26 ; D12.20@140.97,69.85 D12.21@143.51,69.85 145.517,71.857 150.038,71.857 151.13,70.764 D12.24@151.13,69.85
  Bottom Layer w0.508: C23.1@14.605,32.385 14.732,32.258 19.05,32.258 ; V2.C@17.796,138.406 18.566,138.406 19.812,137.16 19.812,133.604 24.003,129.413 v1(26.416,129.413) v1(26.416,123.444) ; 20.082,28.21 19.05,29.242 19.05,32.258 ; v1(27.94,33.02) 19.812,33.02 19.05,32.258 ; C51.1@29.972,63.627 29.972,61.849 30.099,61.722 ; D18.16@37.1,28.21 38.862,29.972 49.308,29.972 D19.16@51.07,28.21 ; v1(76.2,104.14) D17.24@76.2,97.79 81.915,97.79 85.725,101.6 C50.1@85.725,102.87 ; D7.14@104.14,72.39 106.68,72.39 106.68,61.214 R4.2@106.426,60.96
  Bottom Layer w0.6: 176.784,134.874 v2(180.34,138.43) ; v1@183.372,70.12 v1(183.388,70.104)
  Bottom Layer w0.762: R1.2@19.32,59.96 21.082,61.722 30.099,61.722 35.306,61.722 36.576,60.452 ; D1.16@37.1,57.42 37.1,59.928 36.576,60.452 ; v2(46.482,64.008) v3(44.196,64.008) 40.132,64.008 36.576,60.452
  Bottom Layer w0.8: D16.14@21.86,28.21 20.082,28.21 18.812,26.94 18.812,7.89 19.59,7.112 66.818,7.112 67.58,7.874 ; D20.26@74.93,114.3 74.93,120.142 v1(77.47,122.682)
  Bottom Layer w1: DD9.14@59.96,57.42 59.96,60.436 59.944,60.452 60.706,61.214 v2(64.008,61.214) 75.2,61.214
  Bottom Layer w1.016: 171.45,71.66 R12.1@171.45,80.01 SV1.3@171.45,85.09 D8.40@171.45,92.71
  Bottom Layer w1.27: 75.184,60.96 75.2,60.944 D10.14@75.2,57.42
  Bottom Layer w1.5: 67.58,7.874 67.58,7.89 ; D22.8@67.58,10.43 67.58,7.89 ; 75.184,60.96 R5.1@78.232,60.96 89.154,60.96 ; D23.8@81.55,10.43 81.55,7.89 ; D5.14@89.17,57.42 89.17,60.944 89.154,60.96 ; D24.8@95.52,10.43 95.52,7.89 ; D11.16@103.14,57.42 103.14,60.944 103.124,60.96 ; D25.8@109.49,10.43 109.49,7.89 ; DD4.14@117.11,57.42 117.11,60.944 117.094,60.96 ; D26.8@123.46,10.43 123.46,7.89 ; C24.1@128.27,63.5 128.27,60.96 ; D27.8@137.43,10.43 137.43,7.89 ; DD13.14@145.05,57.42 145.05,60.944 145.034,60.96 ; D12.24@151.13,69.85 153.67,69.85 ; D28.8@151.4,10.43 151.4,7.89 ; PP.Б32@161.94,142.28 162.052,142.392 162.052,143.51 ; PP.А32@161.94,144.78 162.052,144.668 162.052,143.51 ; D29.8@165.37,10.43 165.37,7.89 ; D15.24@172.99,70.12 171.45,71.66 169.45,73.66 154.94,73.66 153.67,72.39 153.67,69.85 ; v2(177.8,138.43) 175.514,136.144 ; v2(180.34,22.86) 183.388,22.86 ; v2(180.34,25.4) 183.388,25.4 ; v2(180.34,27.94) 183.388,27.94 ; v2(180.34,30.48) 183.388,30.48 ; v2(180.34,135.89) 178.054,133.604 ; 67.58,7.89 C22.1@78.232,7.89 81.55,7.89 ; 81.55,7.89 95.52,7.89 ; 89.154,60.96 103.124,60.96 ; 95.52,7.89 106.172,7.89 109.49,7.89 ; 103.124,60.96 R4.2@106.426,60.96 117.094,60.96 ; 109.49,7.89 120.142,7.89 123.46,7.89 ; 117.094,60.96 128.27,60.96 ; 123.46,7.89 C19.1@134.112,7.89 137.43,7.89 ; 128.27,60.96 145.034,60.96 ; 137.43,7.89 C18.1@148.082,7.89 151.4,7.89 ; 145.034,60.96 146.574,62.5 R6-R11.1@151.4,62.5 153.67,64.77 153.67,69.85 ; 151.4,7.89 C17.1@162.306,7.89 165.37,7.89 ; 162.052,143.51 168.148,143.51 175.514,136.144 ; 165.37,7.89 176.038,7.89 177.8,9.652 182.88,9.652 183.388,10.16 183.388,22.86 ; 175.514,136.144 176.784,134.874 178.054,133.604 ; 178.054,133.604 183.388,128.27 v1(183.388,117.094) v1(183.388,73.152) v1(183.388,70.104) v1(183.388,66.802) 183.388,30.48 ; 183.388,22.86 183.388,25.4 ; 183.388,25.4 183.388,27.94 ; 183.388,27.94 183.388,30.48
pads on no net: D3.2 D3.3 D3.4 D3.13 D21.1 D21.5 D21.8 D22.1 D23.1 D24.1 D25.1 D26.1 D27.1 D28.1 D29.1
copper on no net:
  other v4: 79.44,147.28 166.94,147.28

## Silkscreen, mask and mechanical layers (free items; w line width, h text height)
Top Overlay:
  circle w0.254: c5,5 r3.354
  circle w0.254: c5,145 r3.354
  circle w0.254: c180,145 r3.354
  circle w0.254: c180,5 r3.354
  circle w0.254: c113,99 r3.354
  lines w0.15: 39.37,35.179 38.1,33.909 42.926,33.909 43.18,33.909 41.91,35.179 ; 39.37,35.179 39.37,36.449 41.91,36.449 41.91,35.179 ; 39.37,35.179 41.91,35.179
  lines w0.2: 41.021,60.198 42.545,59.055
  text "OUT" at 61.595,145.542 h1.3 r90
  text "GND" at 64.135,145.542 h1.3 r90
  text "IN" at 66.675,145.542 h1.3 r90
  text "VID" at 69.215,145.542 h1.3 r90
  text "GND" at 71.755,145.542 h1.3 r90
  text "VCC" at 165.1,140.462 h1.52
  text "GND" at 76.708,139.954 h1.52
  text "25" at 143.51,139.192 h1.5
  text "5" at 93.98,139.065 h1.5
  text "10" at 106.045,139.065 h1.5
  text "15" at 118.745,139.065 h1.5
  text "20" at 130.81,139.065 h1.5
  text "-5v" at 153.67,135.89 h1.52
  text "+12v" at 159.385,135.89 h1.52
  text "RADIO-86RK (RU5_32KB)" at 104.394,133.858 h4
  text "B" at 18.415,131.826 h1.52
  text "1" at 116.078,128.778 h1.52
  text "1" at 177.546,128.524 h1.52
  text "1" at 7.112,118.11 h1.52
  text "1" at 31.496,118.11 h1.52
  text "1" at 178.054,107.315 h1.52
  text "MONITOR" at 64.897,106.172 h1.52
  text "1" at 57.658,97.155 h1.52
  text "1" at 85.598,93.98 h1.52
  text "FONT" at 132.588,87.757 h1.52
  text "+" at 170.815,86.995 h2
  text "1" at 154.94,86.614 h1.52
  text "1" at 157.48,74.168 h1.52
  text "1" at 63.5,57.15 h1.52
  text "1" at 26.416,56.896 h1.52
  text "1" at 40.64,29.21 h1.52
  text "1" at 162.56,29.21 h1.52
  text "1" at 11.43,26.67 h1.52
  text "D2" at 4.572,19.05 h1.52
  text "RU5D" at 1.524,16.51 h1.52
  text "D1" at 4.572,13.97 h1.52
Bottom Solder:
  lines w0.7: 64.008,61.214 74.803,61.214 74.93,61.087
  lines w0.8: 74.93,61.087 75.311,60.96 ; 75.2,57.42 75.184,60.706 75.311,60.96 ; 145.05,57.42 145.034,60.96 ; 183.388,70.104 172.99,70.12 170.466,72.644 169.291,73.787 155.067,73.787 153.67,72.39 153.67,64.77 151.4,62.5 146.558,62.484 145.161,61.087 145.034,60.96 ; 75.311,60.96 78.232,60.96 145.034,60.96
  lines w1: 67.564,10.287 67.564,8.255 67.691,7.874 67.945,7.874 163.703,7.874 176.022,7.874 177.8,9.652 178.181,9.652 183.007,9.652 183.388,10.16 183.388,10.541 183.388,128.397 168.021,143.51 161.94,143.51 ; 84.44,142.28 84.44,144.78 ; 84.44,143.51 76.2,143.51 72.898,146.812 58.674,146.812 14.605,146.812 14.351,146.685 2.54,134.874 2.54,14.351 2.54,13.97 11.43,5.08 41.656,5.08 168.91,5.08 ; 161.94,142.28 161.94,144.78
Mechanical 1:
  the board outline again, w0.15

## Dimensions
0,0 to 0,150 on Mechanical 14
0,0 to 185,0 on Mechanical 14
